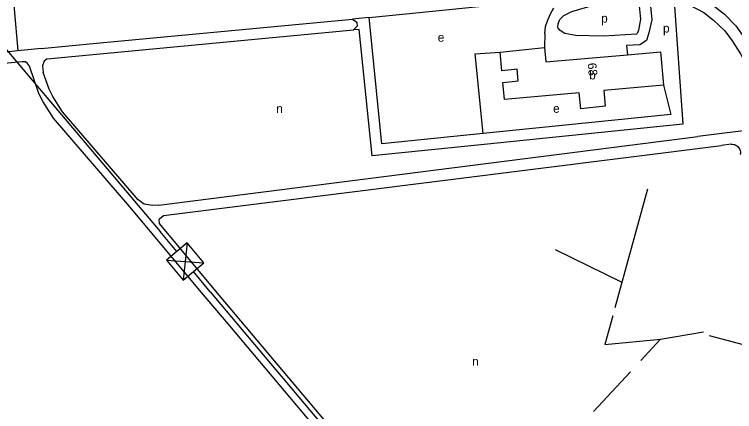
# Model space of a CAD drawing. Extents: x 158142 to 159655, y 385262 to 387204.
# Drawn here: x 158393.2 to 158722.6, y 386403.5 to 386585.1 of the extents above; entities that cross this region are included whole.
import ezdxf

# ---------------------------------------------------------------- set-up
doc = ezdxf.new("R2010")
doc.units = 0
for name, color, linetype in [('BLT_Basislijn', 7, 'Continuous'), ('BLT_Bebouwing', 7, 'Continuous'), ('BLT_Centroide', 7, 'Continuous'), ('BLT_Hoogspanningsmast_en_leidingen', 7, 'Continuous'), ('BLT_Huisnummer', 7, 'Continuous')]:
    doc.layers.add(name, color=color, linetype=linetype)

msp = doc.modelspace()

# ---------------------------------------------------------------- linework, layer by layer
at = {"layer": 'BLT_Basislijn'}
for p, q in [((158555.4, 386583.71), (158636.14, 386591.88)), ((158430.79, 386571.94), (158547.77, 386582.93)), ((158555.4, 386583.71), (158547.77, 386582.93)), ((158408.18, 386564.79), (158548.24, 386577.96)), ((158635.79, 386576.3), (158635.64, 386569.9)), ((158405.36, 386569.55), (158430.79, 386571.94)), ((158673.14, 386570.81), (158673.56, 386566.62)), ((158720.96, 386525.69), (158716.55, 386525.2)), ((158682.72, 386505.11), (158667.8, 386450.93)), ((158670.89, 386462.67), (158640.61, 386477.42)), ((158470.12, 386468.34), (158470.27, 386468.42)), ((158688.66, 386436.59), (158708.41, 386439.93)), ((158710.88, 386438.27), (158726.42, 386434.18)), ((158658.1, 386403.59), (158675, 386421.61))]:
    msp.add_line(p, q, dxfattribs=at)
for points in [[(158404.59, 386699.52), (158384.48, 386683.83), (158394.81, 386568.41)], [(158682.46, 386596.54), (158683.89, 386590.31), (158684.67, 386582.6), (158683.41, 386576.63), (158682.28, 386573.18), (158679.27, 386571.18), (158673.14, 386570.81)], [(158696.08, 386598.01), (158712.54, 386589.37), (158718.01, 386585.14), (158723.17, 386579.86), (158730.26, 386569.56), (158741.33, 386549.4)], [(158694.85, 386593.18), (158698.92, 386534.83), (158608.08, 386525.63)], [(158694.85, 386593.18), (158708.52, 386585.9), (158712.94, 386582.4), (158718.17, 386577.51), (158721.5, 386572.99), (158725.33, 386567.01), (158739.93, 386538.93)], [(158635.79, 386576.3), (158636.16, 386579.46), (158636.96, 386582.06), (158638.38, 386585.39), (158639.85, 386588.02)], [(158547.77, 386582.93), (158549.76, 386581.58), (158549.96, 386579.65), (158548.24, 386577.96)], [(158607.58, 386530.61), (158561.25, 386525.91), (158555.4, 386583.71)], [(158608.08, 386525.63), (158556.78, 386520.44), (158550.93, 386578.21), (158548.24, 386577.96)], [(158405.36, 386569.55), (158394.81, 386568.41)], [(158394.81, 386568.41), (158379.66, 386566.76)], [(158607.58, 386530.61), (158603.89, 386567.03), (158615.28, 386567.83)], [(158478.8, 386457.87), (158445.93, 386497.1), (158411.14, 386537.58), (158406.37, 386545.08), (158404.4, 386548.95), (158400.11, 386561.45), (158399.13, 386562.67), (158398.2, 386563.31), (158396.7, 386563.44), (158380.16, 386561.79)], [(158408.18, 386564.79), (158406.77, 386563.73), (158405.99, 386561.52), (158406.4, 386558.51)], [(158449.75, 386500.33), (158415.17, 386540.57), (158410.71, 386547.56), (158409.02, 386550.9), (158406.4, 386558.51)], [(158690.08, 386552.65), (158693.44, 386539.3), (158607.58, 386530.61)], [(158737.45, 386533.43), (158733.92, 386532.74), (158705.73, 386529.3)], [(158459.21, 386497.87), (158705.73, 386529.3)], [(158484.51, 386459.46), (158459.52, 386489.4), (158459.39, 386491.01), (158459.63, 386491.62), (158461.33, 386493.09), (158716.55, 386525.2)], [(158720.96, 386525.69), (158721.51, 386525.71), (158722.06, 386525.66), (158722.6, 386525.52), (158723.11, 386525.31), (158723.59, 386525.03), (158724.02, 386524.68), (158724.4, 386524.28), (158724.71, 386523.82), (158724.96, 386523.33), (158725.13, 386522.8), (158725.23, 386522.25), (158725.24, 386521.7), (158725.18, 386521.15), (158725.15, 386521.03)], [(158459.21, 386497.87), (158456.13, 386497.72), (158452.52, 386498.3), (158449.75, 386500.33)], [(158624.65, 386284.64), (158490.91, 386443.67), (158478.8, 386457.87)], [(158628.46, 386287.97), (158554.58, 386376.36), (158484.51, 386459.46)], [(158666.89, 386447.21), (158663.25, 386434.22), (158688.66, 386436.59), (158679.64, 386426.85)]]:
    msp.add_lwpolyline(points, dxfattribs=at)
msp.add_lwpolyline([(158641.87, 386578.76), (158641.73, 386579.33), (158641.87, 386580.83), (158642.65, 386582.67), (158644.41, 386584.64), (158648.2, 386586.36), (158660.11, 386589.9), (158669.87, 386592.23), (158673.82, 386593.1), (158676.05, 386592.69), (158677.89, 386591.29), (158679, 386588.95), (158679.61, 386582.87), (158678.57, 386577.93), (158678.06, 386576.38), (158677.63, 386576.09), (158662.57, 386575.19), (158650.03, 386575.39), (158644.95, 386576.29), (158642.77, 386577.71)], close=True, dxfattribs=at)
at = {"layer": 'BLT_Bebouwing'}
msp.add_line((158615.28, 386567.83), (158635.64, 386569.9), dxfattribs=at)
for points in [[(158635.64, 386569.9), (158636.3, 386563.33), (158673.56, 386566.62)], [(158651.56, 386549.25), (158617.33, 386546.21), (158616.55, 386553.98), (158623.61, 386554.69), (158623.07, 386560.04), (158616.14, 386559.34), (158615.28, 386567.83)], [(158673.56, 386566.62), (158688.72, 386567.95), (158690.08, 386552.65)], [(158690.08, 386552.65), (158662.71, 386550.24), (158663.44, 386543.07), (158652.3, 386541.94), (158651.56, 386549.25)]]:
    msp.add_lwpolyline(points, dxfattribs=at)
at = {"layer": 'BLT_Hoogspanningsmast_en_leidingen'}
for p, q in [((158321.96, 386648.57), (158459.79, 386485.85)), ((158467.42, 386476.66), (158459.79, 386485.85)), ((158472.15, 386480.6), (158470.31, 386463.55)), ((158462.68, 386472.73), (158479.78, 386471.42)), ((158482.67, 386458.3), (158475.04, 386467.48)), ((158482.67, 386458.3), (158613.07, 386303.54))]:
    msp.add_line(p, q, dxfattribs=at)
msp.add_lwpolyline([(158470.31, 386463.55), (158479.78, 386471.42), (158472.15, 386480.6), (158462.68, 386472.73)], close=True, dxfattribs=at)

# ---------------------------------------------------------------- texts
at = {"layer": 'BLT_Centroide'}
for s, p in [('p', (158661.57, 386581.32)), ('p', (158689.84, 386576.77)), ('e', (158586.84, 386572.58)), ('b', (158656.1, 386555.34)), ('n', (158512.98, 386540.02)), ('e', (158639.57, 386540.09)), ('n', (158602.55, 386424.47))]:
    msp.add_text(s, height=4, dxfattribs=at).set_placement(p)
at = {"layer": 'BLT_Huisnummer'}
msp.add_text('68', height=4, rotation=275.7842, dxfattribs=at).set_placement((158655.34, 386562.7))

doc.saveas('drawing.dxf')
